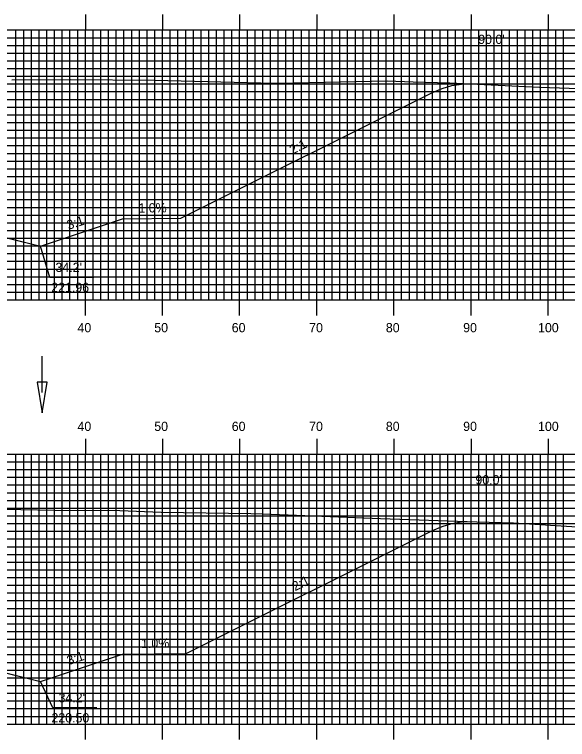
# Model space of a CAD drawing. Extents: x 1816883 to 1817226, y 442591 to 442811.
# Drawn here: x 1817079.4 to 1817151.1, y 442666.7 to 442760.7 of the extents above; entities that cross this region are included whole.
import ezdxf

# ---------------------------------------------------------------- set-up
doc = ezdxf.new("R2010")
doc.units = 0
for name, color, linetype in [('ANNOTATION', 7, 'Continuous'), ('D_Drainage_Ditch_Line', 7, 'Continuous'), ('D_Roadway_Centerline', 7, 'Continuous'), ('D_Roadway_SlopeLines', 7, 'Continuous'), ('D_Text_Standard', 7, 'Continuous'), ('H_V ANNOTATION', 7, 'Continuous'), ('MAJOR', 7, 'Continuous'), ('MINOR', 7, 'Continuous'), ('S_Roadway_Centerline', 7, 'Continuous')]:
    doc.layers.add(name, color=color, linetype=linetype)

msp = doc.modelspace()

# ---------------------------------------------------------------- linework, layer by layer
at = {"layer": 'ANNOTATION'}
for points in [[(1817089.665, 442726.556), (1817083.973, 442726.556), (1817082.76, 442730.62)], [(1817090.058, 442670.751), (1817084.366, 442670.751), (1817082.76, 442674.166)]]:
    msp.add_lwpolyline(points, dxfattribs=at)
at = {"layer": 'D_Drainage_Ditch_Line'}
msp.add_line((1817082.988, 442711.665), (1817082.988, 442716.364), dxfattribs=at)
msp.add_lwpolyline([(1817083.644, 442712.977), (1817082.332, 442712.977), (1817082.988, 442709.04)], close=True, dxfattribs=at)
at = {"layer": 'D_Roadway_Centerline'}
for points in [[(1816958.586, 442751.81), (1816959.836, 442751.753), (1816961.086, 442751.533), (1816962.336, 442751.151), (1816963.586, 442750.607), (1816996.324, 442734.238), (1817003.781, 442734.164), (1817014.412, 442730.62), (1817018.412, 442731.62), (1817028.586, 442734.164), (1817036.586, 442734.484), (1817048.586, 442734.724), (1817060.586, 442734.484), (1817068.586, 442734.164), (1817078.76, 442731.62), (1817082.76, 442730.62), (1817093.391, 442734.164), (1817100.962, 442734.24), (1817133.586, 442750.552), (1817134.836, 442751.091), (1817136.086, 442751.46), (1817137.336, 442751.657), (1817138.586, 442751.684)], [(1816958.586, 442696.643), (1816959.836, 442696.556), (1816961.086, 442696.315), (1816962.336, 442695.92), (1816963.586, 442695.372), (1816998.813, 442677.759), (1817003.781, 442677.709), (1817014.412, 442674.166), (1817018.412, 442675.166), (1817028.586, 442677.709), (1817036.586, 442678.029), (1817048.586, 442678.269), (1817060.586, 442678.029), (1817068.586, 442677.709), (1817078.76, 442675.166), (1817082.76, 442674.166), (1817093.391, 442677.709), (1817101.649, 442677.792), (1817133.586, 442693.76), (1817134.836, 442694.301), (1817136.086, 442694.675), (1817137.336, 442694.882), (1817138.586, 442694.922)]]:
    msp.add_lwpolyline(points, dxfattribs=at)
at = {"layer": 'D_Roadway_SlopeLines'}
for points in [[(1817093.391, 442734.164), (1817100.962, 442734.24), (1817133.586, 442750.552), (1817134.836, 442751.091), (1817136.086, 442751.46), (1817137.336, 442751.657), (1817138.586, 442751.684)], [(1817068.586, 442734.164), (1817082.76, 442730.62)], [(1817082.76, 442730.62), (1817093.391, 442734.164)], [(1817093.391, 442677.709), (1817101.649, 442677.792), (1817133.586, 442693.76), (1817134.836, 442694.301), (1817136.086, 442694.675), (1817137.336, 442694.882), (1817138.586, 442694.922)], [(1817068.586, 442677.709), (1817082.76, 442674.166)], [(1817082.76, 442674.166), (1817093.391, 442677.709)]]:
    msp.add_lwpolyline(points, dxfattribs=at)
at = {"layer": 'MAJOR'}
for p, q in [((1817088.586, 442760.669), (1817088.586, 442758.665)), ((1817098.586, 442760.669), (1817098.586, 442758.665)), ((1817108.586, 442760.669), (1817108.586, 442758.665)), ((1817118.586, 442760.669), (1817118.586, 442758.665)), ((1817128.586, 442760.669), (1817128.586, 442758.665)), ((1817138.586, 442760.669), (1817138.586, 442758.665)), ((1817148.586, 442760.669), (1817148.586, 442758.665)), ((1816908.586, 442758.665), (1817188.586, 442758.665)), ((1816908.586, 442758.665), (1817188.586, 442758.665)), ((1817088.586, 442723.665), (1817088.586, 442758.665)), ((1817098.586, 442723.665), (1817098.586, 442758.665)), ((1817108.586, 442723.665), (1817108.586, 442758.665)), ((1817118.586, 442723.665), (1817118.586, 442758.665)), ((1817128.586, 442723.665), (1817128.586, 442758.665)), ((1817138.586, 442723.665), (1817138.586, 442758.665)), ((1817148.586, 442723.665), (1817148.586, 442758.665)), ((1816908.586, 442753.665), (1817188.586, 442753.665)), ((1816908.586, 442748.665), (1817188.586, 442748.665)), ((1816908.586, 442743.665), (1817188.586, 442743.665)), ((1816908.586, 442738.665), (1817188.586, 442738.665)), ((1816908.586, 442733.665), (1817188.586, 442733.665)), ((1816908.586, 442728.665), (1817188.586, 442728.665)), ((1816908.586, 442723.665), (1817188.586, 442723.665)), ((1816908.586, 442723.665), (1817188.586, 442723.665)), ((1817088.586, 442721.661), (1817088.586, 442723.665)), ((1817098.586, 442721.661), (1817098.586, 442723.665)), ((1817108.586, 442721.661), (1817108.586, 442723.665)), ((1817118.586, 442721.661), (1817118.586, 442723.665)), ((1817128.586, 442721.661), (1817128.586, 442723.665)), ((1817138.586, 442721.661), (1817138.586, 442723.665)), ((1817148.586, 442721.661), (1817148.586, 442723.665)), ((1817088.586, 442705.669), (1817088.586, 442703.665)), ((1817098.586, 442705.669), (1817098.586, 442703.665)), ((1817108.586, 442705.669), (1817108.586, 442703.665)), ((1817118.586, 442705.669), (1817118.586, 442703.665)), ((1817128.586, 442705.669), (1817128.586, 442703.665)), ((1817138.586, 442705.669), (1817138.586, 442703.665)), ((1817148.586, 442705.669), (1817148.586, 442703.665)), ((1816908.586, 442703.665), (1817188.586, 442703.665)), ((1816908.586, 442703.665), (1817188.586, 442703.665)), ((1817088.586, 442668.665), (1817088.586, 442703.665)), ((1817098.586, 442668.665), (1817098.586, 442703.665)), ((1817108.586, 442668.665), (1817108.586, 442703.665)), ((1817118.586, 442668.665), (1817118.586, 442703.665)), ((1817128.586, 442668.665), (1817128.586, 442703.665)), ((1817138.586, 442668.665), (1817138.586, 442703.665)), ((1817148.586, 442668.665), (1817148.586, 442703.665)), ((1816908.586, 442698.665), (1817188.586, 442698.665)), ((1816908.586, 442693.665), (1817188.586, 442693.665)), ((1816908.586, 442688.665), (1817188.586, 442688.665)), ((1816908.586, 442683.665), (1817188.586, 442683.665)), ((1816908.586, 442678.665), (1817188.586, 442678.665)), ((1816908.586, 442673.665), (1817188.586, 442673.665)), ((1816908.586, 442668.665), (1817188.586, 442668.665)), ((1816908.586, 442668.665), (1817188.586, 442668.665)), ((1817088.586, 442666.661), (1817088.586, 442668.665)), ((1817098.586, 442666.661), (1817098.586, 442668.665)), ((1817108.586, 442666.661), (1817108.586, 442668.665)), ((1817118.586, 442666.661), (1817118.586, 442668.665)), ((1817128.586, 442666.661), (1817128.586, 442668.665)), ((1817138.586, 442666.661), (1817138.586, 442668.665)), ((1817148.586, 442666.661), (1817148.586, 442668.665))]:
    msp.add_line(p, q, dxfattribs=at)
at = {"layer": 'MINOR'}
for p, q in [((1817079.586, 442723.665), (1817079.586, 442758.665)), ((1817080.586, 442723.665), (1817080.586, 442758.665)), ((1817081.586, 442723.665), (1817081.586, 442758.665)), ((1817082.586, 442723.665), (1817082.586, 442758.665)), ((1817083.586, 442723.665), (1817083.586, 442758.665)), ((1817084.586, 442723.665), (1817084.586, 442758.665)), ((1817085.586, 442723.665), (1817085.586, 442758.665)), ((1817086.586, 442723.665), (1817086.586, 442758.665)), ((1817087.586, 442723.665), (1817087.586, 442758.665)), ((1817089.586, 442723.665), (1817089.586, 442758.665)), ((1817090.586, 442723.665), (1817090.586, 442758.665)), ((1817091.586, 442723.665), (1817091.586, 442758.665)), ((1817092.586, 442723.665), (1817092.586, 442758.665)), ((1817093.586, 442723.665), (1817093.586, 442758.665)), ((1817094.586, 442723.665), (1817094.586, 442758.665)), ((1817095.586, 442723.665), (1817095.586, 442758.665)), ((1817096.586, 442723.665), (1817096.586, 442758.665)), ((1817097.586, 442723.665), (1817097.586, 442758.665)), ((1817099.586, 442723.665), (1817099.586, 442758.665)), ((1817100.586, 442723.665), (1817100.586, 442758.665)), ((1817101.586, 442723.665), (1817101.586, 442758.665)), ((1817102.586, 442723.665), (1817102.586, 442758.665)), ((1817103.586, 442723.665), (1817103.586, 442758.665)), ((1817104.586, 442723.665), (1817104.586, 442758.665)), ((1817105.586, 442723.665), (1817105.586, 442758.665)), ((1817106.586, 442723.665), (1817106.586, 442758.665)), ((1817107.586, 442723.665), (1817107.586, 442758.665)), ((1817109.586, 442723.665), (1817109.586, 442758.665)), ((1817110.586, 442723.665), (1817110.586, 442758.665)), ((1817111.586, 442723.665), (1817111.586, 442758.665)), ((1817112.586, 442723.665), (1817112.586, 442758.665)), ((1817113.586, 442723.665), (1817113.586, 442758.665)), ((1817114.586, 442723.665), (1817114.586, 442758.665)), ((1817115.586, 442723.665), (1817115.586, 442758.665)), ((1817116.586, 442723.665), (1817116.586, 442758.665)), ((1817117.586, 442723.665), (1817117.586, 442758.665)), ((1817119.586, 442723.665), (1817119.586, 442758.665)), ((1817120.586, 442723.665), (1817120.586, 442758.665)), ((1817121.586, 442723.665), (1817121.586, 442758.665)), ((1817122.586, 442723.665), (1817122.586, 442758.665)), ((1817123.586, 442723.665), (1817123.586, 442758.665)), ((1817124.586, 442723.665), (1817124.586, 442758.665)), ((1817125.586, 442723.665), (1817125.586, 442758.665)), ((1817126.586, 442723.665), (1817126.586, 442758.665)), ((1817127.586, 442723.665), (1817127.586, 442758.665)), ((1817129.586, 442723.665), (1817129.586, 442758.665)), ((1817130.586, 442723.665), (1817130.586, 442758.665)), ((1817131.586, 442723.665), (1817131.586, 442758.665)), ((1817132.586, 442723.665), (1817132.586, 442758.665)), ((1817133.586, 442723.665), (1817133.586, 442758.665)), ((1817134.586, 442723.665), (1817134.586, 442758.665)), ((1817135.586, 442723.665), (1817135.586, 442758.665)), ((1817136.586, 442723.665), (1817136.586, 442758.665)), ((1817137.586, 442723.665), (1817137.586, 442758.665)), ((1817139.586, 442723.665), (1817139.586, 442758.665)), ((1817140.586, 442723.665), (1817140.586, 442758.665)), ((1817141.586, 442723.665), (1817141.586, 442758.665)), ((1817142.586, 442723.665), (1817142.586, 442758.665)), ((1817143.586, 442723.665), (1817143.586, 442758.665)), ((1817144.586, 442723.665), (1817144.586, 442758.665)), ((1817145.586, 442723.665), (1817145.586, 442758.665)), ((1817146.586, 442723.665), (1817146.586, 442758.665)), ((1817147.586, 442723.665), (1817147.586, 442758.665)), ((1817149.586, 442723.665), (1817149.586, 442758.665)), ((1817150.586, 442723.665), (1817150.586, 442758.665)), ((1816908.586, 442757.665), (1817188.586, 442757.665)), ((1816908.586, 442756.665), (1817188.586, 442756.665)), ((1816908.586, 442755.665), (1817188.586, 442755.665)), ((1816908.586, 442754.665), (1817188.586, 442754.665)), ((1816908.586, 442752.665), (1817188.586, 442752.665)), ((1816908.586, 442751.665), (1817188.586, 442751.665)), ((1816908.586, 442750.665), (1817188.586, 442750.665)), ((1816908.586, 442749.665), (1817188.586, 442749.665)), ((1816908.586, 442747.665), (1817188.586, 442747.665)), ((1816908.586, 442746.665), (1817188.586, 442746.665)), ((1816908.586, 442745.665), (1817188.586, 442745.665)), ((1816908.586, 442744.665), (1817188.586, 442744.665)), ((1816908.586, 442742.665), (1817188.586, 442742.665)), ((1816908.586, 442741.665), (1817188.586, 442741.665)), ((1816908.586, 442740.665), (1817188.586, 442740.665)), ((1816908.586, 442739.665), (1817188.586, 442739.665)), ((1816908.586, 442737.665), (1817188.586, 442737.665)), ((1816908.586, 442736.665), (1817188.586, 442736.665)), ((1816908.586, 442735.665), (1817188.586, 442735.665)), ((1816908.586, 442734.665), (1817188.586, 442734.665)), ((1816908.586, 442732.665), (1817188.586, 442732.665)), ((1816908.586, 442731.665), (1817188.586, 442731.665)), ((1816908.586, 442730.665), (1817188.586, 442730.665)), ((1816908.586, 442729.665), (1817188.586, 442729.665)), ((1816908.586, 442727.665), (1817188.586, 442727.665)), ((1816908.586, 442726.665), (1817188.586, 442726.665)), ((1816908.586, 442725.665), (1817188.586, 442725.665)), ((1816908.586, 442724.665), (1817188.586, 442724.665)), ((1817079.586, 442668.665), (1817079.586, 442703.665)), ((1817080.586, 442668.665), (1817080.586, 442703.665)), ((1817081.586, 442668.665), (1817081.586, 442703.665)), ((1817082.586, 442668.665), (1817082.586, 442703.665)), ((1817083.586, 442668.665), (1817083.586, 442703.665)), ((1817084.586, 442668.665), (1817084.586, 442703.665)), ((1817085.586, 442668.665), (1817085.586, 442703.665)), ((1817086.586, 442668.665), (1817086.586, 442703.665)), ((1817087.586, 442668.665), (1817087.586, 442703.665)), ((1817089.586, 442668.665), (1817089.586, 442703.665)), ((1817090.586, 442668.665), (1817090.586, 442703.665)), ((1817091.586, 442668.665), (1817091.586, 442703.665)), ((1817092.586, 442668.665), (1817092.586, 442703.665)), ((1817093.586, 442668.665), (1817093.586, 442703.665)), ((1817094.586, 442668.665), (1817094.586, 442703.665)), ((1817095.586, 442668.665), (1817095.586, 442703.665)), ((1817096.586, 442668.665), (1817096.586, 442703.665)), ((1817097.586, 442668.665), (1817097.586, 442703.665)), ((1817099.586, 442668.665), (1817099.586, 442703.665)), ((1817100.586, 442668.665), (1817100.586, 442703.665)), ((1817101.586, 442668.665), (1817101.586, 442703.665)), ((1817102.586, 442668.665), (1817102.586, 442703.665)), ((1817103.586, 442668.665), (1817103.586, 442703.665)), ((1817104.586, 442668.665), (1817104.586, 442703.665)), ((1817105.586, 442668.665), (1817105.586, 442703.665)), ((1817106.586, 442668.665), (1817106.586, 442703.665)), ((1817107.586, 442668.665), (1817107.586, 442703.665)), ((1817109.586, 442668.665), (1817109.586, 442703.665)), ((1817110.586, 442668.665), (1817110.586, 442703.665)), ((1817111.586, 442668.665), (1817111.586, 442703.665)), ((1817112.586, 442668.665), (1817112.586, 442703.665)), ((1817113.586, 442668.665), (1817113.586, 442703.665)), ((1817114.586, 442668.665), (1817114.586, 442703.665)), ((1817115.586, 442668.665), (1817115.586, 442703.665)), ((1817116.586, 442668.665), (1817116.586, 442703.665)), ((1817117.586, 442668.665), (1817117.586, 442703.665)), ((1817119.586, 442668.665), (1817119.586, 442703.665)), ((1817120.586, 442668.665), (1817120.586, 442703.665)), ((1817121.586, 442668.665), (1817121.586, 442703.665)), ((1817122.586, 442668.665), (1817122.586, 442703.665)), ((1817123.586, 442668.665), (1817123.586, 442703.665)), ((1817124.586, 442668.665), (1817124.586, 442703.665)), ((1817125.586, 442668.665), (1817125.586, 442703.665)), ((1817126.586, 442668.665), (1817126.586, 442703.665)), ((1817127.586, 442668.665), (1817127.586, 442703.665)), ((1817129.586, 442668.665), (1817129.586, 442703.665)), ((1817130.586, 442668.665), (1817130.586, 442703.665)), ((1817131.586, 442668.665), (1817131.586, 442703.665)), ((1817132.586, 442668.665), (1817132.586, 442703.665)), ((1817133.586, 442668.665), (1817133.586, 442703.665)), ((1817134.586, 442668.665), (1817134.586, 442703.665)), ((1817135.586, 442668.665), (1817135.586, 442703.665)), ((1817136.586, 442668.665), (1817136.586, 442703.665)), ((1817137.586, 442668.665), (1817137.586, 442703.665)), ((1817139.586, 442668.665), (1817139.586, 442703.665)), ((1817140.586, 442668.665), (1817140.586, 442703.665)), ((1817141.586, 442668.665), (1817141.586, 442703.665)), ((1817142.586, 442668.665), (1817142.586, 442703.665)), ((1817143.586, 442668.665), (1817143.586, 442703.665)), ((1817144.586, 442668.665), (1817144.586, 442703.665)), ((1817145.586, 442668.665), (1817145.586, 442703.665)), ((1817146.586, 442668.665), (1817146.586, 442703.665)), ((1817147.586, 442668.665), (1817147.586, 442703.665)), ((1817149.586, 442668.665), (1817149.586, 442703.665)), ((1817150.586, 442668.665), (1817150.586, 442703.665)), ((1816908.586, 442702.665), (1817188.586, 442702.665)), ((1816908.586, 442701.665), (1817188.586, 442701.665)), ((1816908.586, 442700.665), (1817188.586, 442700.665)), ((1816908.586, 442699.665), (1817188.586, 442699.665)), ((1816908.586, 442697.665), (1817188.586, 442697.665)), ((1816908.586, 442696.665), (1817188.586, 442696.665)), ((1816908.586, 442695.665), (1817188.586, 442695.665)), ((1816908.586, 442694.665), (1817188.586, 442694.665)), ((1816908.586, 442692.665), (1817188.586, 442692.665)), ((1816908.586, 442691.665), (1817188.586, 442691.665)), ((1816908.586, 442690.665), (1817188.586, 442690.665)), ((1816908.586, 442689.665), (1817188.586, 442689.665)), ((1816908.586, 442687.665), (1817188.586, 442687.665)), ((1816908.586, 442686.665), (1817188.586, 442686.665)), ((1816908.586, 442685.665), (1817188.586, 442685.665)), ((1816908.586, 442684.665), (1817188.586, 442684.665)), ((1816908.586, 442682.665), (1817188.586, 442682.665)), ((1816908.586, 442681.665), (1817188.586, 442681.665)), ((1816908.586, 442680.665), (1817188.586, 442680.665)), ((1816908.586, 442679.665), (1817188.586, 442679.665)), ((1816908.586, 442677.665), (1817188.586, 442677.665)), ((1816908.586, 442676.665), (1817188.586, 442676.665)), ((1816908.586, 442675.665), (1817188.586, 442675.665)), ((1816908.586, 442674.665), (1817188.586, 442674.665)), ((1816908.586, 442672.665), (1817188.586, 442672.665)), ((1816908.586, 442671.665), (1817188.586, 442671.665)), ((1816908.586, 442670.665), (1817188.586, 442670.665)), ((1816908.586, 442669.665), (1817188.586, 442669.665))]:
    msp.add_line(p, q, dxfattribs=at)
at = {"layer": 'S_Roadway_Centerline'}
for points in [[(1817079.033, 442752.196), (1817086.697, 442752.229), (1817097.526, 442752.144), (1817113.075, 442751.766), (1817113.174, 442751.765), (1817113.244, 442751.765), (1817113.603, 442751.773), (1817127.715, 442752.07), (1817131.091, 442751.954), (1817135.838, 442751.813), (1817147.472, 442751.265), (1817153.88, 442751.03), (1817163.982, 442750.508), (1817166.615, 442750.368), (1817177.059, 442750.041), (1817180.959, 442749.914), (1817181.886, 442749.899), (1817183.457, 442749.83), (1817188.586, 442749.673)], [(1817075.827, 442696.557), (1817084.589, 442696.386), (1817093.06, 442696.358), (1817098.409, 442696.153), (1817110.047, 442695.953), (1817111.593, 442695.935), (1817126.859, 442695.336), (1817139.346, 442694.895), (1817144.101, 442694.749), (1817153.023, 442694.193), (1817160.683, 442693.664), (1817165.109, 442693.591), (1817176.869, 442692.94), (1817184.756, 442692.536), (1817188.586, 442692.36)]]:
    msp.add_lwpolyline(points, dxfattribs=at)

# ---------------------------------------------------------------- texts
at = {"layer": 'ANNOTATION'}
for s, rotation, p in [('2:1', 26.56505, (1817115.419, 442742.504)), ('1.0%', 0.57294, (1817095.466, 442734.985)), ('3:1', 18.43492, (1817086.414, 442732.747)), ('2:1', 26.56505, (1817115.763, 442685.885)), ('1.0%', 0.57294, (1817095.809, 442678.533)), ('3:1', 18.43494, (1817086.414, 442676.292))]:
    msp.add_text(s, height=1.2, rotation=rotation, dxfattribs=at).set_placement(p)
for s, p in [("34.2'", (1817084.708, 442727.282)), ('221.96', (1817084.156, 442724.682)), ("34.2'", (1817085.101, 442671.477)), ('220.50', (1817084.185, 442668.877))]:
    msp.add_text(s, height=1.2, dxfattribs=at).set_placement(p)
at = {"layer": 'D_Text_Standard'}
for p in [(1817139.514, 442756.849), (1817139.148, 442699.739)]:
    msp.add_text("90.0'", height=1.2, dxfattribs=at).set_placement(p)
at = {"layer": 'H_V ANNOTATION'}
for s, p in [('40', (1817087.558, 442719.465)), ('50', (1817097.515, 442719.465)), ('60', (1817107.558, 442719.465)), ('70', (1817117.59, 442719.465)), ('80', (1817127.537, 442719.465)), ('90', (1817137.558, 442719.465)), ('100', (1817147.269, 442719.465)), ('40', (1817087.558, 442706.665)), ('50', (1817097.515, 442706.665)), ('60', (1817107.558, 442706.665)), ('70', (1817117.59, 442706.665)), ('80', (1817127.537, 442706.665)), ('90', (1817137.558, 442706.665)), ('100', (1817147.269, 442706.665))]:
    msp.add_text(s, height=1.2, dxfattribs=at).set_placement(p)

doc.saveas('drawing.dxf')
